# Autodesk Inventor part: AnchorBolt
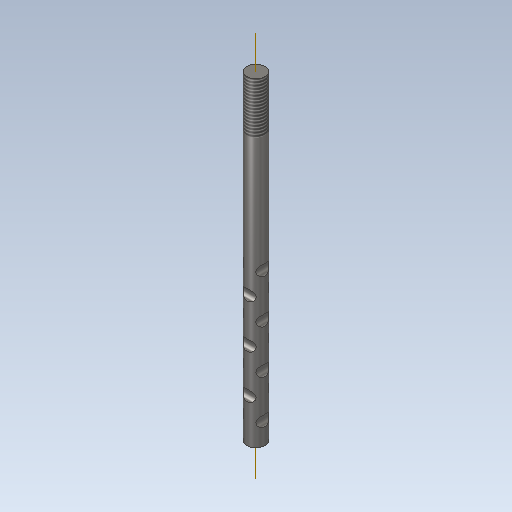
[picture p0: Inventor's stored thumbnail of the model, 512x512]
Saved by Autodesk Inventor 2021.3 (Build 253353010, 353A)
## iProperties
Created: 2019-05
Part Number: AnchorBolt
Material: Steel, Galvanized
Document SubType Name: Modeling
Designer: u1426
Density: 7.85 g/cm^3
Appearance: Galvanized
Protrusion: 7.000 in
BoltDiameter: 1.250 in
EmbedConcrete: 15.000 in
NoSwedgesLeast: 3.000 ul
Author: u1426
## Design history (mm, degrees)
sketch "Sketch1"
  geometry: C1 r 15.875 at (0, 0); 1 further point
  constraints: 1 centre point, 1 coincident, 1 other
extrude "Extrusion1" new body sketch "Sketch1" taper "d3" = 0 deg; dims "d4" = 0
thread "Thread1" dims "d5" = 88.9 (derived), "d6" = 0
sketch "Sketch4"
  geometry: L1 (177.8, 15.875)-(-381, 15.875) reference; L2 (177.8, 15.875)-(-381, 15.875) reference; L3 (-295.275, 15.875)-(-314.325, 15.875); L4 (165.1, 19.05)-(-381, 19.05); L5 (165.1, 19.05)-(-381, 19.05); L6 (165.1, 19.05)-(-381, 19.05); L7 (165.1, 19.05)-(-381, 19.05); A1 r 11.906 centre (-304.8, 23.019) between (-314.325, 15.875) and (-295.275, 15.875); 11 further points
  constraints: 10 end point, 2 point on circle, 1 centre point, 6 other
  dimensions: "d29" = 19.05 distance of L3.start L3.end; "d30" = 11.90625 radius of A1; "d31" = 76.2 horizontal distance of A1.centre L1.end; "d32" = 9.525 horizontal distance of L3.end A1.centre
extrude "Extrusion2" cut sketch "Sketch4" extent not by distance; stored distance "d9" = 25.4; taper "d10" = 0 deg
mirror "Mirror1"
pattern_linear "Rectangular Pattern1" dims "d39" = 76.2
sketch "Sketch6"
  geometry: L1 (-381, 15.875)-(-381, -15.875) reference; L2 (177.8, 15.875)-(-381, 15.875) reference; L3 (-333.375, 15.875)-(-352.425, 15.875); A1 r 11.906 centre (-342.9, 23.019) between (-352.425, 15.875) and (-333.375, 15.875); 1 further point
  constraints: 2 end point, 2 point on circle, 2 point on line, 1 centre point, 1 horizontal
  dimensions: "d46" = 19.05 distance of L3.end L3.start; "d48" = 38.1 horizontal distance of A1.centre L2.end; "d49" = 11.90625 radius of A1
extrude "Extrusion4" cut sketch "Sketch6" extent not by distance; stored distance "d44" = 25.4; taper "d45" = 0 deg
mirror "Mirror2"
pattern_linear "Rectangular Pattern3" dims "d55" = 76.2
body "Solid1"
workaxis "Work Axis5"
workaxis "Work Axis36"
